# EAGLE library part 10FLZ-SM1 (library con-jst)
CONNECTOR
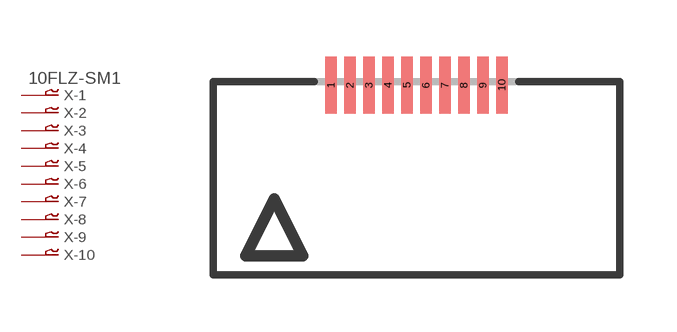
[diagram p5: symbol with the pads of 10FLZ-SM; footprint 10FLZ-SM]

Designator prefix X; gates -1=P-VN -2=P-N -3=P-N -4=P-N -5=P-N -6=P-N -7=P-N -8=P-N -9=P-N -10=P-N

## 10FLZ-SM1 (OC_FARNELL: unknown; OC_NEWARK: unknown)  [10FLZ-SM]
1  -1:1  pas
2  -2:1  pas
3  -3:1  pas
4  -4:1  pas
5  -5:1  pas
6  -6:1  pas
7  -7:1  pas
8  -8:1  pas
9  -9:1  pas
10  -10:1  pas

## Footprint 10FLZ-SM (pad centres in mm)
CONNECTOR
smd 0.3 x 1.5: 1 -2.25,2.5; 2 -1.75,2.5; 3 -1.25,2.5; 4 -0.75,2.5; 5 -0.25,2.5; 6 0.25,2.5; 7 0.75,2.5; 8 1.25,2.5; 9 1.75,2.5; 10 2.25,2.5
